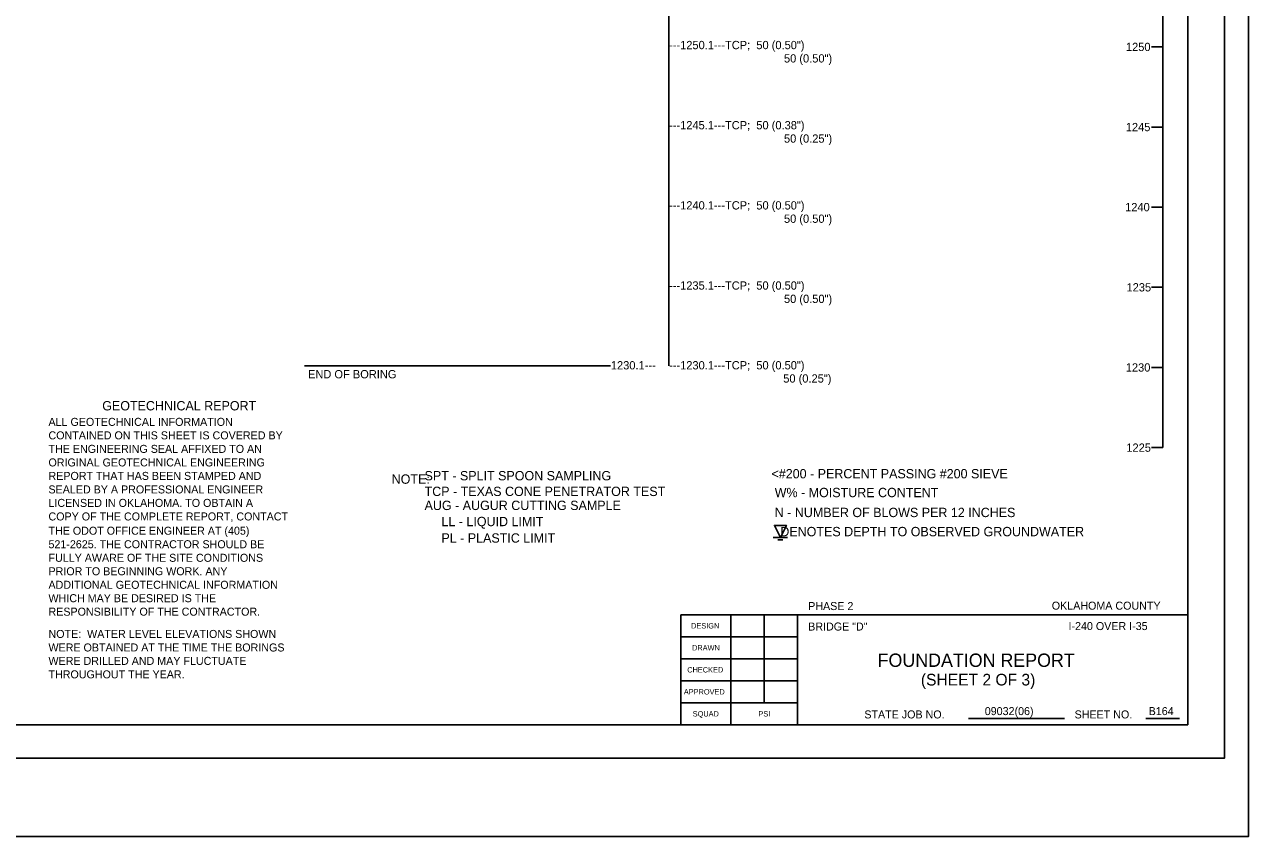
# Model space of a CAD drawing. Extents: x -93 to 177, y 25 to 84.
# Drawn here: x -33.62 to -15.26, y 25.37 to 37.55 of the extents above; entities that cross this region are included whole.
import ezdxf

# ---------------------------------------------------------------- set-up
doc = ezdxf.new("R2010")
doc.units = 0
for name, color, linetype in [('SHT_Plot_Shape_Full', 7, 'Continuous'), ('SHT_Plot_Shape_Half', 7, 'Continuous'), ('SHT_Sheet_Border', 7, 'Continuous'), ('SHT_Standard_Sheet_Lines', 7, 'Continuous'), ('SHT_Standard_Sheet_Txt', 7, 'Continuous'), ('T-Subtitle', 7, 'Continuous'), ('T-Title', 7, 'Continuous'), ('Text', 7, 'Continuous')]:
    doc.layers.add(name, color=color, linetype=linetype)

# ---------------------------------------------------------------- blocks, each defined once
blk = doc.blocks.new('DGRFC_WTLEV1')
for points in [[(-0.0127, 0), (0.0127, 0)], [(0, 0), (0.0106, 0.0212), (-0.0106, 0.0212), (0, 0)], [(-0.0042, -0.0042), (0.0042, -0.0042)]]:
    blk.add_lwpolyline(points)

msp = doc.modelspace()

# ---------------------------------------------------------------- linework, layer by layer
msp.add_line((-16.548, 31.2), (-16.548, 45.623))
for points in [[(-23.955, 45.063), (-23.955, 32.429)], [(-23.955, 44.339), (-23.955, 33.248)], [(-16.548, 37.209), (-16.714, 37.209)], [(-16.548, 36.007), (-16.714, 36.007)], [(-16.548, 34.806), (-16.714, 34.806)], [(-16.548, 33.604), (-16.714, 33.604)], [(-29.416, 32.429), (-24.831, 32.429)], [(-16.548, 32.402), (-16.714, 32.402)], [(-16.548, 31.2), (-16.714, 31.2)]]:
    msp.add_lwpolyline(points)
at = {"layer": 'SHT_Plot_Shape_Full'}
msp.add_lwpolyline([(-51.261, 49.368), (-15.261, 49.368), (-15.261, 25.368), (-51.261, 25.368)], close=True, dxfattribs=at)
at = {"layer": 'SHT_Plot_Shape_Half'}
msp.add_lwpolyline([(-49.623, 48.543), (-15.623, 48.543), (-15.623, 26.543), (-49.623, 26.543)], close=True, dxfattribs=at)
at = {"layer": 'SHT_Sheet_Border'}
for p, q in [((-23.773, 27.043), (-23.773, 28.693)), ((-23.773, 28.693), (-16.173, 28.693)), ((-22.023, 27.043), (-22.023, 28.694))]:
    msp.add_line(p, q, dxfattribs=at)
msp.add_lwpolyline([(-16.173, 27.043), (-47.673, 27.043), (-47.673, 48.043), (-16.173, 48.043)], close=True, dxfattribs=at)
at = {"layer": 'SHT_Standard_Sheet_Lines'}
for p, q in [((-23.023, 27.043), (-23.023, 28.694)), ((-22.523, 27.373), (-22.523, 28.694)), ((-19.462, 27.139), (-18.022, 27.139)), ((-16.798, 27.139), (-16.295, 27.139))]:
    msp.add_line(p, q, dxfattribs=at)
for points in [[(-22.023, 28.363), (-23.773, 28.363)], [(-22.023, 28.033), (-23.773, 28.033)], [(-22.023, 27.703), (-23.773, 27.703)], [(-22.023, 27.373), (-23.773, 27.373)]]:
    msp.add_lwpolyline(points, dxfattribs=at)

# ---------------------------------------------------------------- block references
at = {"xscale": 8.503919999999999, "yscale": 8.503919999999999}
msp.add_blockref('DGRFC_WTLEV1', (-22.281, 29.853), dxfattribs=at)

# ---------------------------------------------------------------- texts
for s, p in [('---1250.1---TCP;  50 (0.50")', (-23.95, 37.175)), ('1250', (-17.099, 37.147)), ('50 (0.50")', (-22.227, 36.975)), ('---1245.1---TCP;  50 (0.38")', (-23.95, 35.973)), ('1245', (-17.101, 35.945)), ('50 (0.25")', (-22.227, 35.773)), ('---1240.1---TCP;  50 (0.50")', (-23.95, 34.771)), ('50 (0.50")', (-22.227, 34.571)), ('1240', (-17.111, 34.744)), ('---1235.1---TCP;  50 (0.50")', (-23.95, 33.569)), ('1235', (-17.09, 33.542)), ('50 (0.50")', (-22.227, 33.369)), ('1230.1---', (-24.823, 32.373)), ('---1230.1---TCP;  50 (0.50")', (-23.95, 32.373)), ('END OF BORING', (-29.365, 32.239)), ('1230', (-17.101, 32.34)), ('50 (0.25")', (-22.238, 32.175)), ('1225', (-17.093, 31.138))]:
    msp.add_text(s, height=0.124).set_placement(p)
at = {"layer": 'SHT_Standard_Sheet_Txt'}
for s, height, p in [('PHASE 2', 0.12, (-21.864, 28.764)), ('OKLAHOMA COUNTY', 0.12, (-18.211, 28.77)), ('DESIGN', 0.08, (-23.62, 28.488)), ('BRIDGE "D" ', 0.12, (-21.864, 28.457)), ('I-240 OVER I-35', 0.12, (-17.96, 28.464)), ('DRAWN', 0.08, (-23.606, 28.158)), ('CHECKED', 0.08, (-23.678, 27.828)), ('APPROVED', 0.08, (-23.729, 27.498)), ('SQUAD', 0.08, (-23.596, 27.168)), ('PSI', 0.08, (-22.611, 27.168)), ('STATE JOB NO.', 0.12, (-21.022, 27.139)), ('09032(06)', 0.12, (-19.216, 27.189)), ('SHEET NO. ', 0.12, (-17.869, 27.139)), ('B164', 0.12, (-16.758, 27.189))]:
    msp.add_text(s, height=height, dxfattribs=at).set_placement(p)
at = {"layer": 'T-Subtitle'}
msp.add_text('(SHEET 2 OF 3)', height=0.175, dxfattribs=at).set_placement((-20.174, 27.633))
at = {"layer": 'T-Title'}
msp.add_text('FOUNDATION REPORT', height=0.2, dxfattribs=at).set_placement((-20.823, 27.912))
at = {"layer": 'Text'}
for s, height, p in [('GEOTECHNICAL REPORT', 0.14, (-32.451, 31.758)), ('ALL GEOTECHNICAL INFORMATION ', 0.12, (-33.257, 31.526)), ('CONTAINED ON THIS SHEET IS COVERED BY ', 0.12, (-33.257, 31.324)), ('THE ENGINEERING SEAL AFFIXED TO AN ', 0.12, (-33.257, 31.121)), ('ORIGINAL GEOTECHNICAL ENGINEERING ', 0.12, (-33.257, 30.918)), ('    SPT - SPLIT SPOON SAMPLING', 0.14, (-27.825, 30.709)), (' <#200 - PERCENT PASSING #200 SIEVE', 0.14, (-22.466, 30.739)), ('REPORT THAT HAS BEEN STAMPED AND ', 0.12, (-33.257, 30.716)), ('NOTE:', 0.14, (-28.11, 30.658)), ('SEALED BY A PROFESSIONAL ENGINEER ', 0.12, (-33.257, 30.513)), ('    TCP - TEXAS CONE PENETRATOR TEST', 0.14, (-27.825, 30.474)), ('W% - MOISTURE CONTENT', 0.14, (-22.366, 30.457)), ('LICENSED IN OKLAHOMA. TO OBTAIN A ', 0.12, (-33.257, 30.311)), ('    AUG - AUGUR CUTTING SAMPLE', 0.14, (-27.825, 30.264)), ('N - NUMBER OF BLOWS PER 12 INCHES', 0.14, (-22.366, 30.158)), ('COPY OF THE COMPLETE REPORT, CONTACT ', 0.12, (-33.257, 30.108)), (' LL - LIQUID LIMIT', 0.14, (-27.416, 30.022)), ('THE ODOT OFFICE ENGINEER AT (405) ', 0.12, (-33.257, 29.894)), ('    DENOTES DEPTH TO OBSERVED GROUNDWATER', 0.14, (-22.49, 29.871)), ('521-2625. THE CONTRACTOR SHOULD BE ', 0.12, (-33.257, 29.691)), (' PL - PLASTIC LIMIT', 0.14, (-27.416, 29.775)), ('FULLY AWARE OF THE SITE CONDITIONS ', 0.12, (-33.257, 29.488)), ('PRIOR TO BEGINNING WORK. ANY ', 0.12, (-33.257, 29.286)), ('ADDITIONAL GEOTECHNICAL INFORMATION ', 0.12, (-33.257, 29.083)), ('WHICH MAY BE DESIRED IS THE ', 0.12, (-33.257, 28.882)), ('RESPONSIBILITY OF THE CONTRACTOR.', 0.12, (-33.257, 28.68)), ('NOTE:  WATER LEVEL ELEVATIONS SHOWN ', 0.12, (-33.257, 28.346)), ('WERE OBTAINED AT THE TIME THE BORINGS ', 0.12, (-33.257, 28.143)), ('WERE DRILLED AND MAY FLUCTUATE ', 0.12, (-33.257, 27.942)), ('THROUGHOUT THE YEAR.', 0.12, (-33.257, 27.74))]:
    msp.add_text(s, height=height, dxfattribs=at).set_placement(p)

doc.saveas('drawing.dxf')
